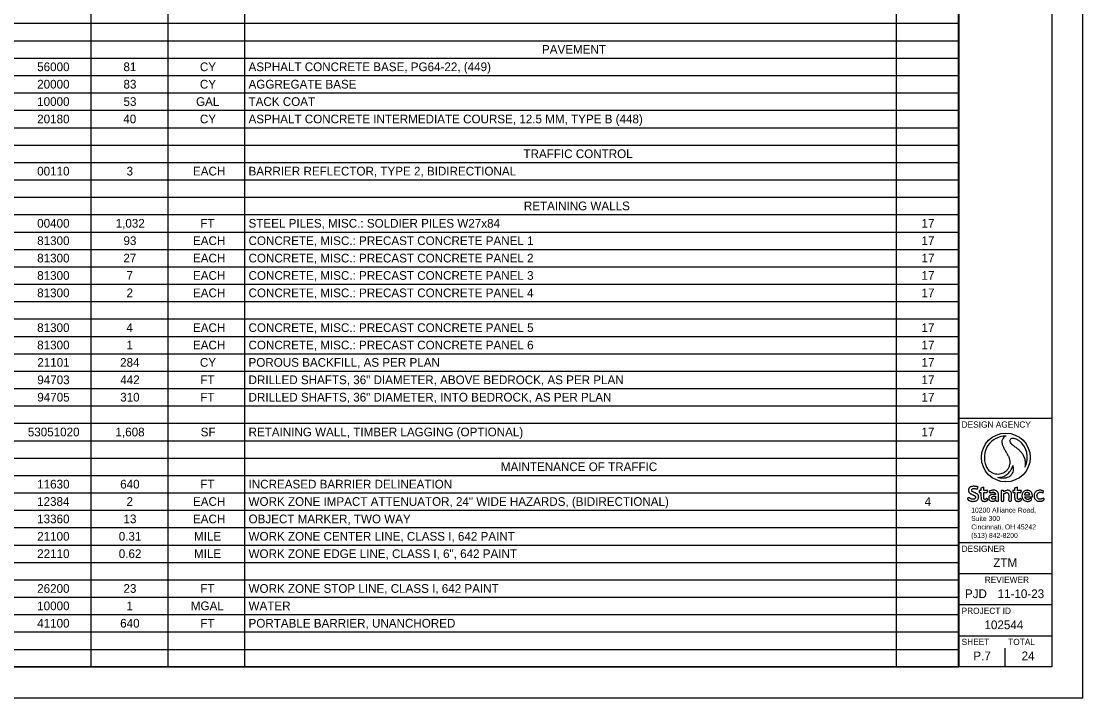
# Model space of a CAD drawing. Extents: x 0 to 34, y 0 to 22.
# Drawn here: x 16.91 to 34, y 0 to 10.89 of the extents above; entities that cross this region are included whole.
import ezdxf

# ---------------------------------------------------------------- set-up
doc = ezdxf.new("R2010")
doc.units = 0
for name, color, linetype in [('SH_Border', 7, 'Continuous'), ('SH_Cut_Line', 7, 'Continuous'), ('SH_Data', 7, 'Continuous'), ('SH_Text', 7, 'Continuous')]:
    doc.layers.add(name, color=color, linetype=linetype)

msp = doc.modelspace()

# ---------------------------------------------------------------- linework, layer by layer
at = {"layer": 'SH_Border'}
for p, q in [((32, 0.5), (32, 21.5)), ((32, 4.5), (33.5, 4.5)), ((32, 2.5), (33.5, 2.5)), ((32, 2), (33.5, 2)), ((32, 1.5), (33.5, 1.5)), ((32, 1), (33.5, 1))]:
    msp.add_line(p, q, dxfattribs=at)
msp.add_lwpolyline([(1.5, 21.5), (33.5, 21.5), (33.5, 0.5), (1.5, 0.5)], close=True, dxfattribs=at)
at = {"layer": 'SH_Cut_Line'}
msp.add_lwpolyline([(0, 0), (34, 0), (34, 22), (0, 22)], close=True, dxfattribs=at)
at = {"layer": 'SH_Data'}
for p, q in [((18.036, 21.5), (18.036, 0.5)), ((19.272, 21.5), (19.272, 0.5)), ((20.507, 21.5), (20.507, 0.5)), ((30.999, 21.5), (30.999, 0.5)), ((32.004, 21.5), (32.004, 0.5)), ((1.5, 10.86), (32.004, 10.86)), ((1.5, 10.58), (32.004, 10.58)), ((1.5, 10.3), (32.004, 10.3)), ((1.5, 10.02), (32.004, 10.02)), ((1.5, 9.74), (32.004, 9.74)), ((1.5, 9.46), (32.004, 9.46)), ((1.5, 9.18), (32.004, 9.18)), ((1.5, 8.9), (32.004, 8.9)), ((1.5, 8.62), (32.004, 8.62)), ((1.5, 8.34), (32.004, 8.34)), ((1.5, 8.06), (32.004, 8.06)), ((1.5, 7.78), (32.004, 7.78)), ((1.5, 7.5), (32.004, 7.5)), ((1.5, 7.22), (32.004, 7.22)), ((1.5, 6.94), (32.004, 6.94)), ((1.5, 6.66), (32.004, 6.66)), ((1.5, 6.38), (32.004, 6.38)), ((1.5, 6.1), (32.004, 6.1)), ((1.5, 5.82), (32.004, 5.82)), ((1.5, 5.54), (32.004, 5.54)), ((1.5, 5.26), (32.004, 5.26)), ((1.5, 4.98), (32.004, 4.98)), ((1.5, 4.7), (32.004, 4.7)), ((1.5, 4.42), (32.004, 4.42)), ((1.5, 4.14), (32.004, 4.14)), ((1.5, 3.86), (32.004, 3.86)), ((1.5, 3.58), (32.004, 3.58)), ((32.75, 3.5), (32.75, 3.5)), ((1.5, 3.3), (32.004, 3.3)), ((1.5, 3.02), (32.004, 3.02)), ((1.5, 2.74), (32.004, 2.74)), ((1.5, 2.46), (32.004, 2.46)), ((1.5, 2.18), (32.004, 2.18)), ((1.5, 1.9), (32.004, 1.9)), ((1.5, 1.62), (32.004, 1.62)), ((1.5, 1.34), (32.004, 1.34)), ((1.5, 1.06), (32.004, 1.06)), ((1.5, 0.78), (32.004, 0.78)), ((32.75, 0.5), (32.75, 0.8)), ((32.375, 0.675), (32.375, 0.675)), ((1.5, 0.5), (32.004, 0.5))]:
    msp.add_line(p, q, dxfattribs=at)
at = {"layer": 'SH_Text'}
for p, q in [((32.302, 3.358), (32.314, 3.392)), ((32.362, 3.336), (32.331, 3.336)), ((32.331, 3.336), (32.331, 3.303)), ((32.331, 3.303), (32.362, 3.303)), ((32.409, 3.389), (32.362, 3.376)), ((32.362, 3.376), (32.362, 3.336)), ((32.409, 3.336), (32.409, 3.389)), ((32.472, 3.336), (32.409, 3.336)), ((32.409, 3.219), (32.409, 3.303)), ((32.409, 3.303), (32.46, 3.303)), ((32.46, 3.303), (32.472, 3.336)), ((32.492, 3.325), (32.506, 3.297)), ((32.596, 3.247), (32.596, 3.209)), ((32.725, 3.337), (32.684, 3.337)), ((32.684, 3.337), (32.684, 3.184)), ((32.728, 3.317), (32.725, 3.337)), ((32.731, 3.184), (32.731, 3.285)), ((32.903, 3.336), (32.873, 3.336)), ((32.873, 3.336), (32.873, 3.303)), ((32.873, 3.303), (32.904, 3.303)), ((32.951, 3.389), (32.903, 3.376)), ((32.903, 3.376), (32.903, 3.336)), ((32.95, 3.219), (32.951, 3.303)), ((32.951, 3.336), (32.951, 3.389)), ((33.013, 3.336), (32.951, 3.336)), ((32.951, 3.303), (33.002, 3.303)), ((33.002, 3.303), (33.013, 3.336)), ((33.141, 3.265), (33.068, 3.265)), ((33.359, 3.296), (33.37, 3.327)), ((33.068, 3.236), (33.19, 3.236))]:
    msp.add_line(p, q, dxfattribs=at)
for points in [[(32.769, 4.215), (32.769, 4.215)], [(32.968, 4.147), (32.968, 4.147)]]:
    msp.add_lwpolyline(points, dxfattribs=at)
msp.add_circle((32.762, 3.869), 0.392, dxfattribs=at)
for start, end in [(88.7666, 203.6845), (88.7601, 88.7666), (333.7815, 53.4326), (247.1184, 251.458)]:
    msp.add_arc((32.762, 3.869), 0.346, start, end, dxfattribs=at)
for points, degree in [([(32.769, 4.215), (32.761, 4.213), (32.741, 4.209), (32.715, 4.183), (32.696, 4.14), (32.699, 4.091), (32.716, 4.045), (32.742, 3.999), (32.768, 3.949), (32.798, 3.902), (32.819, 3.854), (32.828, 3.802), (32.822, 3.749), (32.807, 3.702), (32.777, 3.658), (32.739, 3.627), (32.698, 3.609), (32.661, 3.597), (32.62, 3.597), (32.575, 3.604), (32.53, 3.624), (32.482, 3.665), (32.459, 3.705), (32.445, 3.73)], 3), ([(32.769, 4.215), (32.769, 4.215), (32.769, 4.215), (32.769, 4.215)], 2), ([(33.072, 3.716), (33.075, 3.728), (33.08, 3.751), (33.079, 3.788), (33.076, 3.82), (33.066, 3.85), (33.055, 3.884), (33.036, 3.922), (33.008, 3.957), (32.971, 3.994), (32.926, 4.027), (32.879, 4.065), (32.841, 4.093), (32.828, 4.127), (32.828, 4.152), (32.841, 4.169), (32.857, 4.181), (32.879, 4.183), (32.905, 4.178), (32.936, 4.165), (32.957, 4.153), (32.968, 4.147)], 3), ([(32.627, 3.55), (32.636, 3.549), (32.656, 3.548), (32.69, 3.554), (32.728, 3.563), (32.763, 3.583), (32.795, 3.606), (32.824, 3.637), (32.849, 3.673), (32.865, 3.71), (32.869, 3.732), (32.872, 3.742)], 3), ([(32.872, 3.742), (32.874, 3.734), (32.881, 3.711), (32.882, 3.674), (32.876, 3.633), (32.855, 3.596), (32.827, 3.562), (32.786, 3.543), (32.742, 3.533), (32.697, 3.532), (32.666, 3.538), (32.652, 3.541)], 3), ([(32.314, 3.392), (32.312, 3.393), (32.302, 3.398), (32.284, 3.402), (32.262, 3.405), (32.242, 3.406), (32.225, 3.404), (32.209, 3.401), (32.193, 3.395), (32.179, 3.385), (32.168, 3.371), (32.162, 3.357), (32.16, 3.344), (32.161, 3.332), (32.163, 3.321), (32.168, 3.311), (32.174, 3.303), (32.181, 3.295), (32.19, 3.288), (32.201, 3.282), (32.214, 3.275), (32.229, 3.268), (32.244, 3.262), (32.256, 3.255), (32.266, 3.248), (32.272, 3.24), (32.274, 3.231), (32.274, 3.223), (32.27, 3.214), (32.263, 3.206), (32.25, 3.2), (32.236, 3.198), (32.219, 3.199), (32.205, 3.202), (32.194, 3.208), (32.184, 3.212), (32.178, 3.218), (32.172, 3.22), (32.166, 3.222), (32.161, 3.222), (32.155, 3.22), (32.15, 3.216), (32.146, 3.209), (32.146, 3.203), (32.147, 3.196), (32.152, 3.189), (32.162, 3.179), (32.181, 3.17), (32.203, 3.164), (32.226, 3.163), (32.245, 3.163), (32.262, 3.165), (32.277, 3.17), (32.293, 3.177), (32.308, 3.189), (32.319, 3.203), (32.324, 3.22), (32.325, 3.236), (32.323, 3.25), (32.317, 3.261), (32.311, 3.273), (32.299, 3.282), (32.286, 3.291), (32.271, 3.298), (32.255, 3.305), (32.239, 3.312), (32.225, 3.32), (32.216, 3.328), (32.212, 3.337), (32.211, 3.345), (32.213, 3.353), (32.219, 3.36), (32.226, 3.365), (32.236, 3.369), (32.248, 3.369), (32.26, 3.369), (32.271, 3.367), (32.282, 3.365), (32.293, 3.362), (32.299, 3.359), (32.302, 3.358)], 3), ([(32.362, 3.303), (32.362, 3.273), (32.362, 3.242), (32.362, 3.207), (32.364, 3.198), (32.367, 3.187), (32.373, 3.179), (32.38, 3.173), (32.387, 3.168), (32.398, 3.164), (32.413, 3.163), (32.429, 3.163), (32.445, 3.165), (32.457, 3.172), (32.466, 3.179), (32.47, 3.187), (32.471, 3.194), (32.469, 3.2), (32.466, 3.204), (32.462, 3.206), (32.458, 3.207), (32.453, 3.207), (32.448, 3.206), (32.444, 3.202), (32.439, 3.199), (32.433, 3.196), (32.427, 3.194), (32.42, 3.195), (32.415, 3.198), (32.41, 3.202), (32.408, 3.21), (32.408, 3.215), (32.409, 3.219)], 3), ([(32.596, 3.275), (32.593, 3.275), (32.583, 3.275), (32.566, 3.274), (32.545, 3.273), (32.526, 3.269), (32.508, 3.261), (32.492, 3.248), (32.485, 3.229), (32.486, 3.211), (32.489, 3.196), (32.498, 3.183), (32.512, 3.171), (32.531, 3.164), (32.551, 3.163), (32.57, 3.166), (32.584, 3.171), (32.594, 3.178), (32.598, 3.183), (32.601, 3.185)], 3), ([(32.601, 3.185), (32.601, 3.184), (32.601, 3.18), (32.605, 3.174), (32.611, 3.167), (32.621, 3.163), (32.632, 3.163), (32.642, 3.165), (32.646, 3.173), (32.646, 3.181), (32.644, 3.192), (32.641, 3.221), (32.643, 3.252), (32.643, 3.285), (32.639, 3.302), (32.63, 3.316), (32.62, 3.327), (32.604, 3.336), (32.584, 3.341), (32.56, 3.342), (32.536, 3.34), (32.513, 3.335), (32.498, 3.328), (32.492, 3.325)], 3), ([(32.506, 3.297), (32.508, 3.298), (32.515, 3.302), (32.526, 3.305), (32.539, 3.308), (32.551, 3.309), (32.564, 3.309), (32.576, 3.305), (32.586, 3.299), (32.593, 3.291), (32.596, 3.282), (32.596, 3.277), (32.596, 3.275)], 3), ([(32.596, 3.209), (32.595, 3.208), (32.591, 3.205), (32.583, 3.2), (32.571, 3.196), (32.559, 3.195), (32.549, 3.198), (32.541, 3.202), (32.537, 3.208), (32.533, 3.215), (32.533, 3.222), (32.534, 3.229), (32.539, 3.236), (32.546, 3.24), (32.555, 3.244), (32.566, 3.246), (32.578, 3.246), (32.589, 3.247), (32.594, 3.247), (32.596, 3.247)], 3), ([(32.731, 3.285), (32.732, 3.286), (32.736, 3.289), (32.743, 3.293), (32.754, 3.3), (32.766, 3.304), (32.78, 3.304), (32.792, 3.3), (32.801, 3.291), (32.806, 3.28), (32.808, 3.265), (32.807, 3.244), (32.808, 3.216), (32.806, 3.193), (32.807, 3.177), (32.813, 3.169), (32.822, 3.163), (32.833, 3.163), (32.844, 3.165), (32.853, 3.172), (32.855, 3.184), (32.853, 3.207), (32.854, 3.234), (32.854, 3.264), (32.855, 3.283), (32.852, 3.3), (32.847, 3.311), (32.839, 3.323), (32.825, 3.333), (32.809, 3.341), (32.79, 3.341), (32.772, 3.34), (32.757, 3.335), (32.743, 3.329), (32.734, 3.321), (32.729, 3.318), (32.728, 3.317)], 3), ([(32.904, 3.303), (32.904, 3.273), (32.903, 3.242), (32.904, 3.207), (32.905, 3.198), (32.909, 3.187), (32.915, 3.179), (32.922, 3.173), (32.929, 3.168), (32.94, 3.164), (32.955, 3.163), (32.971, 3.163), (32.987, 3.165), (32.999, 3.172), (33.008, 3.179), (33.012, 3.187), (33.012, 3.194), (33.011, 3.2), (33.008, 3.204), (33.004, 3.206), (33, 3.207), (32.995, 3.207), (32.99, 3.206), (32.986, 3.202), (32.981, 3.199), (32.975, 3.196), (32.969, 3.194), (32.962, 3.195), (32.957, 3.198), (32.952, 3.202), (32.95, 3.21), (32.95, 3.215), (32.95, 3.219)], 3), ([(33.19, 3.236), (33.19, 3.24), (33.19, 3.252), (33.188, 3.271), (33.183, 3.292), (33.173, 3.308), (33.162, 3.322), (33.147, 3.332), (33.129, 3.339), (33.108, 3.341), (33.088, 3.34), (33.069, 3.334), (33.052, 3.325), (33.038, 3.311), (33.028, 3.295), (33.023, 3.277), (33.021, 3.258), (33.021, 3.238), (33.025, 3.22), (33.032, 3.202), (33.043, 3.186), (33.06, 3.174), (33.081, 3.164), (33.106, 3.163), (33.128, 3.163), (33.147, 3.167), (33.162, 3.174), (33.173, 3.184), (33.177, 3.194), (33.175, 3.202), (33.171, 3.209), (33.164, 3.211), (33.158, 3.211), (33.151, 3.209), (33.142, 3.204), (33.132, 3.197), (33.119, 3.195), (33.108, 3.194), (33.096, 3.197), (33.087, 3.204), (33.078, 3.211), (33.072, 3.221), (33.069, 3.23), (33.068, 3.234), (33.068, 3.236)], 3), ([(33.068, 3.265), (33.068, 3.267), (33.068, 3.27), (33.068, 3.278), (33.071, 3.287), (33.076, 3.296), (33.085, 3.304), (33.097, 3.309), (33.11, 3.309), (33.123, 3.305), (33.133, 3.299), (33.138, 3.287), (33.14, 3.276), (33.141, 3.269), (33.141, 3.265)], 3), ([(33.37, 3.327), (33.366, 3.33), (33.356, 3.335), (33.337, 3.34), (33.312, 3.343), (33.287, 3.34), (33.262, 3.332), (33.242, 3.318), (33.227, 3.3), (33.218, 3.278), (33.215, 3.255), (33.216, 3.23), (33.225, 3.209), (33.237, 3.192), (33.254, 3.178), (33.277, 3.167), (33.304, 3.163), (33.329, 3.164), (33.35, 3.17), (33.366, 3.177), (33.377, 3.187), (33.377, 3.197), (33.377, 3.205), (33.372, 3.209), (33.367, 3.212), (33.361, 3.212), (33.354, 3.211), (33.347, 3.205), (33.337, 3.201), (33.327, 3.197), (33.314, 3.196), (33.299, 3.197), (33.285, 3.204), (33.275, 3.215), (33.266, 3.228), (33.264, 3.243), (33.262, 3.257), (33.266, 3.272), (33.271, 3.285), (33.28, 3.296), (33.291, 3.304), (33.304, 3.309), (33.319, 3.31), (33.334, 3.309), (33.348, 3.304), (33.356, 3.299), (33.359, 3.296)], 3), ([(32.684, 3.184), (32.685, 3.182), (32.686, 3.177), (32.689, 3.17), (32.698, 3.163), (32.71, 3.163), (32.722, 3.164), (32.729, 3.172), (32.731, 3.179), (32.731, 3.182), (32.731, 3.184)], 3)]:
    msp.add_open_spline(points, degree=degree, dxfattribs=at)

# ---------------------------------------------------------------- texts
at = {"layer": 'SH_Data'}
for s, height, p in [('DESIGN AGENCY', 0.1, (32.05, 4.35)), ('DESIGNER', 0.1, (32.05, 2.35)), ('ZTM', 0.14, (32.56, 2.105)), ('REVIEWER', 0.1, (32.422, 1.85)), ('PJD', 0.14, (32.103, 1.605)), ('11-10-23', 0.14, (32.629, 1.605)), ('PROJECT ID', 0.1, (32.05, 1.35)), ('102544', 0.14, (32.418, 1.105)), ('SHEET', 0.1, (32.05, 0.85)), ('TOTAL', 0.1, (32.8, 0.85)), ('P.7', 0.14, (32.239, 0.605)), ('24', 0.14, (33.016, 0.605))]:
    msp.add_text(s, height=height, dxfattribs=at).set_placement(p)
at = {"layer": 'SH_Text'}
for s, p in [('PAVEMENT', (25.296, 10.37)), ('56000', (17.171, 10.09)), ('81', (18.559, 10.09)), ('CY', (19.79, 10.09)), ('ASPHALT CONCRETE BASE, PG64-22, (449)', (20.573, 10.09)), ('20000', (17.171, 9.81)), ('83', (18.56, 9.81)), ('CY', (19.79, 9.81)), ('AGGREGATE BASE', (20.573, 9.81)), ('10000', (17.171, 9.53)), ('53', (18.56, 9.53)), ('GAL', (19.728, 9.53)), ('TACK COAT', (20.573, 9.53)), ('ASPHALT CONCRETE INTERMEDIATE COURSE, 12.5 MM, TYPE B (448)', (20.573, 9.25)), ('20180', (17.171, 9.25)), ('40', (18.557, 9.25)), ('CY', (19.79, 9.25)), ('TRAFFIC CONTROL', (24.998, 8.69)), ('00110', (17.171, 8.41)), ('3', (18.61, 8.41)), ('EACH', (19.679, 8.41)), ('BARRIER REFLECTOR, TYPE 2, BIDIRECTIONAL', (20.573, 8.41)), ('RETAINING WALLS', (25.004, 7.85)), ('00400', (17.171, 7.57)), ('1,032', (18.434, 7.57)), ('FT', (19.796, 7.57)), ('STEEL PILES, MISC.: SOLDIER PILES W27x84', (20.573, 7.57)), ('17', (31.405, 7.57)), ('81300', (17.171, 7.29)), ('93', (18.56, 7.29)), ('EACH', (19.679, 7.29)), ('CONCRETE, MISC.: PRECAST CONCRETE PANEL 1', (20.573, 7.29)), ('17', (31.405, 7.29)), ('81300', (17.171, 7.01)), ('27', (18.558, 7.01)), ('EACH', (19.679, 7.01)), ('CONCRETE, MISC.: PRECAST CONCRETE PANEL 2', (20.573, 7.01)), ('17', (31.405, 7.01)), ('81300', (17.171, 6.73)), ('7', (18.608, 6.73)), ('EACH', (19.679, 6.73)), ('CONCRETE, MISC.: PRECAST CONCRETE PANEL 3', (20.573, 6.73)), ('17', (31.405, 6.73)), ('81300', (17.171, 6.45)), ('2', (18.609, 6.45)), ('EACH', (19.679, 6.45)), ('CONCRETE, MISC.: PRECAST CONCRETE PANEL 4', (20.573, 6.45)), ('17', (31.405, 6.45)), ('81300', (17.171, 5.89)), ('4', (18.607, 5.89)), ('EACH', (19.679, 5.89)), ('CONCRETE, MISC.: PRECAST CONCRETE PANEL 5', (20.573, 5.89)), ('17', (31.405, 5.89)), ('81300', (17.171, 5.61)), ('1', (18.609, 5.61)), ('EACH', (19.679, 5.61)), ('CONCRETE, MISC.: PRECAST CONCRETE PANEL 6', (20.573, 5.61)), ('17', (31.405, 5.61)), ('21101', (17.173, 5.33)), ('284', (18.506, 5.33)), ('CY', (19.79, 5.33)), ('POROUS BACKFILL, AS PER PLAN', (20.573, 5.33)), ('17', (31.405, 5.33)), ('94703', (17.173, 5.05)), ('442', (18.509, 5.05)), ('FT', (19.796, 5.05)), ('DRILLED SHAFTS, 36" DIAMETER, ABOVE BEDROCK, AS PER PLAN', (20.573, 5.05)), ('17', (31.405, 5.05)), ('94705', (17.173, 4.77)), ('310', (18.507, 4.77)), ('FT', (19.796, 4.77)), ('DRILLED SHAFTS, 36" DIAMETER, INTO BEDROCK, AS PER PLAN', (20.573, 4.77)), ('17', (31.405, 4.77)), ('53051020', (17.02, 4.21)), ('1,608', (18.432, 4.21)), ('SF', (19.803, 4.21)), ('RETAINING WALL, TIMBER LAGGING (OPTIONAL)', (20.573, 4.21)), ('17', (31.405, 4.21)), ('MAINTENANCE OF TRAFFIC', (24.634, 3.65)), ('11630', (17.171, 3.37)), ('640', (18.507, 3.37)), ('FT', (19.796, 3.37)), ('INCREASED BARRIER DELINEATION', (20.573, 3.37)), ('12384', (17.17, 3.09)), ('2', (18.609, 3.09)), ('EACH', (19.679, 3.09)), ('WORK ZONE IMPACT ATTENUATOR, 24" WIDE HAZARDS, (BIDIRECTIONAL)', (20.573, 3.09)), ('4', (31.454, 3.09)), ('13360', (17.171, 2.81)), ('13', (18.56, 2.81)), ('EACH', (19.679, 2.81)), ('OBJECT MARKER, TWO WAY', (20.573, 2.81)), ('21100', (17.171, 2.53)), ('0.31', (18.484, 2.53)), ('MILE', (19.695, 2.53)), ('WORK ZONE CENTER LINE, CLASS I, 642 PAINT', (20.573, 2.53)), ('22110', (17.171, 2.25)), ('0.62', (18.484, 2.25)), ('WORK ZONE EDGE LINE, CLASS I, 6", 642 PAINT', (20.573, 2.25)), ('MILE', (19.695, 2.25)), ('26200', (17.171, 1.69)), ('23', (18.56, 1.69)), ('FT', (19.796, 1.69)), ('WORK ZONE STOP LINE, CLASS I, 642 PAINT', (20.573, 1.69)), ('10000', (17.171, 1.41)), ('1', (18.609, 1.41)), ('MGAL', (19.644, 1.41)), ('WATER', (20.573, 1.41)), ('41100', (17.171, 1.13)), ('640', (18.507, 1.13)), ('FT', (19.796, 1.13)), ('PORTABLE BARRIER, UNANCHORED', (20.573, 1.13))]:
    msp.add_text(s, height=0.14, dxfattribs=at).set_placement(p)
for s, height, p in [('Suite 300', 0.0795, (32.204, 2.847)), ('10200 Alliance Road,', 0.07948, (32.204, 2.982)), ('Cincinnati, OH 45242', 0.07948, (32.204, 2.711)), ('(513) 842-8200', 0.07948, (32.204, 2.575))]:
    msp.add_text(s, height=height, rotation=360, dxfattribs=at).set_placement(p)

doc.saveas('drawing.dxf')
